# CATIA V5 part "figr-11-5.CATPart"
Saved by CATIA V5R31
Part number: Part4
Bounding box of the stored display mesh (mm): x -40 to 40, y -90 to 150, z -30.056 to 96
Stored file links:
  D:\PROJECTS\Project 2021\US EDITION\CATIA V5 6R 2021\Resources\Part Files\c11_catia_v5_6r2021_prt\figr-11-5.CATPart
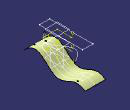
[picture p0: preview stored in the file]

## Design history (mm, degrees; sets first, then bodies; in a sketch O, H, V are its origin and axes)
Body1 (main body)
  Sketch1 on yz-plane, origin (0, 0, 0), H (0, 1, 0), V (0, 0, 1)
    spline S1 through (-90, 0) (-30, 20) (50, -30) (110, -10) (150, -20)
  Extrude1: Element1 Sketch1, Lim1 40, Lim2 40
  Plane1: type Offset, RefPlane xy-plane, Offset 50
  Sketch2 on Plane1, origin (0, 0, 50), H (1, 0, 0), V (0, 1, 0)
    spline S1 through (30, 100) (-10, 40) (20, -10) (-10, -60)
  Plane2: type Offset, RefPlane Plane1, Offset 46
  Sketch3 on Plane2, origin (0, 0, 96), H (1, 0, 0), V (0, 1, 0)
    line L1 (-20, 120) -> (20, 120)
    line L2 (20, 120) -> (20, -50)
    line L3 (20, -50) -> (-20, -50)
    line L4 (-20, -50) -> (-20, 120)
    horizontal: L1 H, L3 H
    vertical: L2 V, L4 V
  MultiSel1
